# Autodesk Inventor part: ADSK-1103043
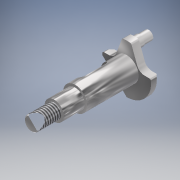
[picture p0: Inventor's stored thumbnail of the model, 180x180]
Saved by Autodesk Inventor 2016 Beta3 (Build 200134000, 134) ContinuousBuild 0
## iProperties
Shininess: 50.0
Length Units: 11272
Angle Units: 11279
Time Units: 11290
Mass Units: 11286
Length Display Precision: 4
Angle Display Precision: 2
Compacted: True
Created: 2000-11
Part Number: ADSK-1103043
Document SubType Name: Modeling
Description: CRANKSHAFT
Mass: 18.2834 g
Surface Area: 21.3592 cm^2
Volume: 2.33206 cm^3
Density: 7.84 g/cm^3
Material: Steel, High Strength Low Alloy
Appearance: Steel - Polished
Density: 0.0
Volumn: 0.0
Area: 0.0
PropertySet Name: Model Information
Control State: 0
Master: False
Checked Out: False
Author: Autodesk, Inc.
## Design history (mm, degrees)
node "Extrusion1" dims "d1" = 30.2625, "d2" = 0
  sketch "Sketch2"
    geometry: C1 r 4.001 at (0, 0); 1 further point
    constraints: 1 centre point, 1 coincident
    dimensions: "d0" = 8.001 diameter of C1
node "Extrusion2" dims "d4" = 3.175, "d5" = 0
  sketch "Sketch3"
    geometry: C1 r 4.001 at (0, 0) reference; C2 r 10.224 at (0, 0)
    constraints: 1 centre point, 1 coincident
    dimensions: "d3" = 20.447 diameter of C2
node "Extrusion6" dims "d23" = 21.5, "d24" = 0
  sketch "Sketch7"
    geometry: C1 r 4.001 at (0, 0) reference; C2 r 5.001 at (0, 0)
    constraints: 1 centre point, 1 coincident
    dimensions: "d22" = 10.00125 diameter of C2
node "Extrusion3" dims "d9" = 3.175, "d10" = 0
  sketch "Sketch4"
    geometry: L1 (-10.144, 1.27)-(-5.15, 1.27); L2 (-5.15, 1.27)-(-1.905, 10.044); L3 (1.905, 10.044)-(5.15, 1.27); L4 (5.15, 1.27)-(10.144, 1.27); C1 r 4.001 at (0, 0) reference; A1 r 10.224 centre (0, 0) between (-10.144, 1.27) and (-1.905, 10.044) reference
    constraints: 8 end point, 4 point on circle, 2 collinear, 2 equal length, 1 horizontal
    dimensions: "d6" = 1.27 distance from line of L4 A1.centre; "d7" = 3.81 distance of L3.start L2.end; "d8" = 1.27 distance edge to line of C1 L2
node "Fillet1" dims "d11" = 0.7874
node "Extrusion4" dims "d13" = 21.336, "d14" = 0
  sketch "Sketch5"
    geometry: C1 r 4.001 at (0, 0) reference; C2 r 3.175 at (0, 0)
    constraints: 1 centre point, 1 coincident
    dimensions: "d12" = 6.35 diameter of C2
node "Chamfer1" dims "d15" = 1.27, "d16" = 5.08, "d44" = 45 deg
node "Fillet2" dims "d17" = 9.525
node "Extrusion5" dims "d20" = 6, "d21" = 0
  sketch "Sketch6"
    geometry: C1 r 1.905 at (0, 7.62); A1 r 10.224 centre (0, 0) between (1.905, 10.044) and (-1.905, 10.044) reference
    constraints: 1 centre point, 1 vertical alignment
    dimensions: "d18" = 3.81 diameter of C1; "d19" = 7.62 distance of A1.centre C1.centre
node "Fillet3" dims "d25" = 3.175
workaxis "Work Axis1"
workaxis "Work Axis2"
workplane "Work Plane1"
node "Revolution1" dims "d28" = 200 deg
  sketch "Sketch8"
    geometry: L1 (10.224, 0)-(10.224, -3.175) reference; L2 (10.224, -3.175)-(-0.523, -3.175) reference; L3 (9.411, -3.175)-(10.224, -2.362); L4 (0, -17.062)-(0, 38.15) reference
    constraints: 2 end point, 2 point on line
    dimensions: "d26" = 0.8128 distance of L1.end L3.end; "d27" = 0.8128 distance from line of L1 L3.start (= d26)
sketch "Sketch9"
  geometry: C1 r 1.905 at (0, 7.62) reference; A1 r 0.787 centre (-1.325, 9.343) between (-1.436, 10.122) and (-2.064, 9.616) reference; 1 further point
  constraints: 1 coincident, 3 other
extrude "Extrusion7" join sketch "Sketch9" distance "d29" = 2.19235; taper "d30" = 0 deg
sketch "Sketch10"
  geometry: C1 r 4.001 at (0, 0) reference; C2 r 3 at (0, 0)
  constraints: 1 centre point, 1 coincident
  dimensions: "d31" = 6 diameter of C2
extrude "Extrusion8" join sketch "Sketch10" distance "d32" = 9.525; taper "d33" = 0 deg
thread "Thread1" dims "d34" = 25.4, "d35" = 0
chamfer "Chamfer2" distance "d36" = 0.381; stored, may be unused: second distance "d37" = 0.381, angle "d45" = 45 deg
sketch "Sketch11"
  geometry: L1 (0, -14.313)-(0, 14.313) reference; L2 (0, 0)-(-4.982, 0.436); C1 r 4.001 at (0, 0) reference
  constraints: 2 end point, 2 other
  dimensions: "d38" = 85 deg angle of L1 L2
workplane "Work Plane2"
sketch "Sketch12"
  geometry: L1 (-5.001, -21.5)-(-5.001, 0) reference; L2 (5.001, -21.5)-(5.001, 0) reference; L3 (-5.001, -4.164)-(5.001, -4.164); L4 (5.001, -4.164)-(5.001, -15.658); L5 (5.001, -15.658)-(-5.001, -15.658); L6 (-5.001, -15.658)-(-5.001, -4.164); L7 (4.001, 0)-(-4.001, 0) reference; L8 (10.224, -21.5)-(0.369, -21.5) reference; 1 further point
  constraints: 8 end point, 2 parallel, 2 point on line, 1 horizontal, 1 perpendicular
  dimensions: "d39" = 4.164 distance between parallel lines of L7 L3; "d40" = 5.842 distance between parallel lines of L8 L5
extrude "Extrusion9" cut sketch "Sketch12" distance "d41" = 3.175; taper "d42" = 0 deg
fillet "Fillet4" dims "d43" = 1.27
body "Solid1"
